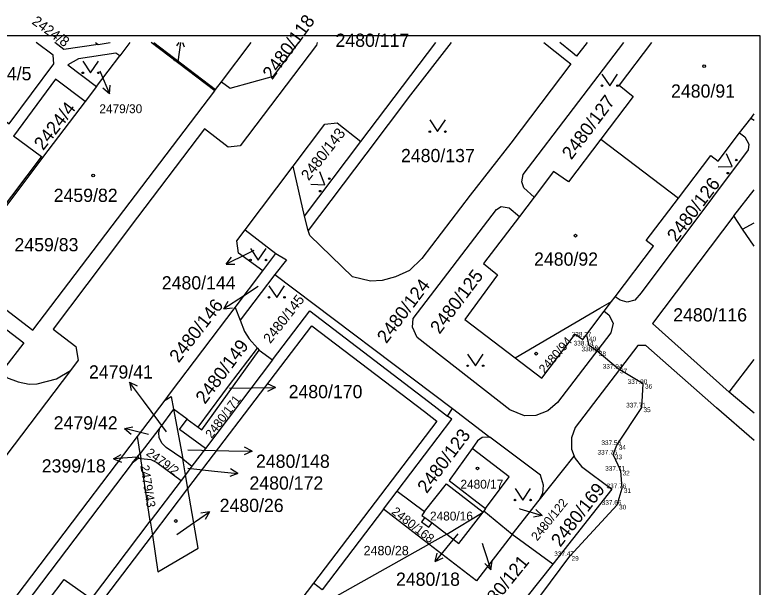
# Model space of a CAD drawing. Extents: x -606208 to -605570, y -1157873 to -1157573.
# Drawn here: x -605669 to -605573.3, y -1157647.4 to -1157573.8 of the extents above; entities that cross this region are included whole.
import ezdxf

# ---------------------------------------------------------------- set-up
doc = ezdxf.new("R2010")
doc.units = 0
for name, color, linetype in [('Vrstva 1', 7, 'Continuous'), ('Vrstva 30', 7, 'Continuous'), ('Vrstva 58', 7, 'Continuous'), ('Vrstva 59', 7, 'Continuous'), ('Vrstva 60', 7, 'Continuous'), ('Vrstva 62', 7, 'Continuous')]:
    doc.layers.add(name, color=color, linetype=linetype)

msp = doc.modelspace()

# ---------------------------------------------------------------- linework, layer by layer
at = {"layer": 'Vrstva 1'}
msp.add_lwpolyline([(-606203.28, -1157873.46), (-605573.29, -1157873.46), (-605573.29, -1157576.47), (-606203.28, -1157576.47)], close=True, dxfattribs=at)
at = {"layer": 'Vrstva 30'}
msp.add_lwpolyline([(-605601.46, -1157648.4), (-605597.74, -1157643.37), (-605591.64, -1157636.77), (-605591.02, -1157634.65), (-605591.19, -1157632.39), (-605592.18, -1157630.32), (-605591.68, -1157629.09), (-605588.5, -1157624.26), (-605588.31, -1157621.23), (-605591.51, -1157619.27), (-605594.23, -1157617.04), (-605595.25, -1157616.29), (-605595.5, -1157615.15)], dxfattribs=at)
at = {"layer": 'Vrstva 60'}
for p, q in [((-605595.5, -1157615.15), (-605595.5, -1157615.15)), ((-605595.25, -1157616.29), (-605595.25, -1157616.29)), ((-605594.23, -1157617.04), (-605594.23, -1157617.04)), ((-605591.51, -1157619.27), (-605591.51, -1157619.27)), ((-605588.31, -1157621.23), (-605588.31, -1157621.23)), ((-605588.5, -1157624.26), (-605588.5, -1157624.26)), ((-605591.68, -1157629.09), (-605591.68, -1157629.09)), ((-605592.18, -1157630.32), (-605592.18, -1157630.32)), ((-605591.19, -1157632.39), (-605591.19, -1157632.39)), ((-605591.02, -1157634.65), (-605591.02, -1157634.65)), ((-605591.64, -1157636.77), (-605591.64, -1157636.77)), ((-605597.74, -1157643.37), (-605597.74, -1157643.37))]:
    msp.add_line(p, q, dxfattribs=at)
at = {"layer": 'Vrstva 62'}
for p, q in [((-605658.68, -1157577.34), (-605658.35, -1157577.6)), ((-605658.35, -1157577.6), (-605656.81, -1157577.34)), ((-605654.27, -1157577.34), (-605655.56, -1157579.05)), ((-605643.36, -1157583.54), (-605651.52, -1157577.34)), ((-605651.18, -1157577.34), (-605643.24, -1157583.38)), ((-605647.98, -1157577.34), (-605648.28, -1157577.77)), ((-605648.06, -1157579.82), (-605647.71, -1157577.34)), ((-605647.48, -1157577.34), (-605647.29, -1157577.91)), ((-605624.6, -1157590.04), (-605614.97, -1157577.34)), ((-605658.55, -1157582.99), (-605655.56, -1157579.05)), ((-605658.13, -1157580.99), (-605658.05, -1157581.18)), ((-605658.05, -1157581.18), (-605656.877, -1157583.942)), ((-605656.877, -1157583.942), (-605656.808, -1157582.825)), ((-605643.24, -1157583.38), (-605642.49, -1157582.39)), ((-605658.55, -1157582.99), (-605660.02, -1157584.93)), ((-605656.877, -1157583.942), (-605657.73, -1157583.216)), ((-605643.36, -1157583.54), (-605643.24, -1157583.38)), ((-605660.02, -1157584.93), (-605665.48, -1157592.12)), ((-605575.92, -1157588.96), (-605574.5, -1157587.09)), ((-605665.62, -1157592.02), (-605669.22, -1157589.38)), ((-605631.83, -1157599.66), (-605624.6, -1157590.04)), ((-605593.76, -1157589.76), (-605583.79, -1157597.35)), ((-605665.48, -1157592.12), (-605676.6, -1157606.77)), ((-605665.48, -1157592.12), (-605665.62, -1157592.02)), ((-605639.44, -1157601.41), (-605633.29, -1157593.25)), ((-605631.83, -1157599.66), (-605633.29, -1157593.25)), ((-605602.33, -1157597.22), (-605604.21, -1157599.69)), ((-605631.37, -1157601.51), (-605631.83, -1157599.66)), ((-605575.53, -1157601.33), (-605576.67, -1157599.63)), ((-605575.53, -1157601.33), (-605574.07, -1157600.52)), ((-605639.44, -1157601.41), (-605635.52, -1157604.45)), ((-605639.19, -1157604.51), (-605641.887, -1157605.826)), ((-605638.32, -1157604.09), (-605639.19, -1157604.51)), ((-605637.18, -1157606.68), (-605635.52, -1157604.45)), ((-605641.887, -1157605.826), (-605641.207, -1157604.936)), ((-605641.887, -1157605.826), (-605640.768, -1157605.837)), ((-605640.74, -1157611.39), (-605637.18, -1157606.68)), ((-605635.64, -1157607.15), (-605640.08, -1157613.05)), ((-605635.64, -1157607.15), (-605612.79, -1157624.41)), ((-605637.78, -1157608.71), (-605639.67, -1157609.93)), ((-605639.67, -1157609.93), (-605642.187, -1157611.564)), ((-605642.187, -1157611.564), (-605641.62, -1157610.599)), ((-605592.38, -1157610.65), (-605591.9, -1157610.02)), ((-605642.187, -1157611.564), (-605641.074, -1157611.439)), ((-605640.74, -1157611.39), (-605640.08, -1157613.05)), ((-605593.32, -1157611.89), (-605592.38, -1157610.65)), ((-605646.81, -1157634.69), (-605630.89, -1157613.78)), ((-605630.89, -1157613.78), (-605616.42, -1157624.79)), ((-605637.86, -1157616.65), (-605637.63, -1157616.91)), ((-605637.63, -1157616.91), (-605635.93, -1157618.15)), ((-605635.93, -1157618.15), (-605644.56, -1157629.53)), ((-605577.25, -1157622.29), (-605574.07, -1157618.1)), ((-605661.91, -1157619.51), (-605672.83, -1157633.91)), ((-605652.51, -1157623.39), (-605654.316, -1157620.993)), ((-605654.316, -1157620.993), (-605653.313, -1157621.492)), ((-605654.316, -1157620.993), (-605654.113, -1157622.094)), ((-605641.46, -1157621.77), (-605638.57, -1157621.74)), ((-605638.57, -1157621.74), (-605635.569, -1157621.688)), ((-605635.569, -1157621.688), (-605636.58, -1157621.204)), ((-605635.569, -1157621.688), (-605636.562, -1157622.206)), ((-605653.28, -1157627.99), (-605649.74, -1157623.3)), ((-605649.54, -1157627.39), (-605652.51, -1157623.39)), ((-605648.64, -1157624.47), (-605650.4, -1157626.89)), ((-605646.89, -1157625.75), (-605648.64, -1157624.47)), ((-605648.64, -1157624.47), (-605647.47, -1157630.88)), ((-605616.42, -1157624.79), (-605614.81, -1157626.01)), ((-605613.46, -1157625.36), (-605612.79, -1157624.41)), ((-605612.79, -1157624.41), (-605608.01, -1157628.06)), ((-605646.89, -1157625.75), (-605645.48, -1157626.78)), ((-605654.962, -1157626.984), (-605653.869, -1157626.74)), ((-605650.4, -1157626.89), (-605652.95, -1157630.16)), ((-605614.81, -1157626.01), (-605630.66, -1157646.86)), ((-605652.05, -1157627.71), (-605654.962, -1157626.984)), ((-605654.962, -1157626.984), (-605654.111, -1157627.712)), ((-605651.89, -1157627.75), (-605652.05, -1157627.71)), ((-605652.95, -1157630.16), (-605653.28, -1157627.99)), ((-605646.81, -1157629.7), (-605641.56, -1157629.83)), ((-605644.56, -1157629.53), (-605646.3, -1157631.82)), ((-605638.559, -1157629.882), (-605639.552, -1157629.364)), ((-605610.28, -1157629.53), (-605613.26, -1157633.64)), ((-605605.51, -1157633.16), (-605610.28, -1157629.53)), ((-605656.354, -1157630.859), (-605655.39, -1157630.29)), ((-605653.36, -1157630.65), (-605656.354, -1157630.859)), ((-605653.95, -1157631.43), (-605652.95, -1157630.16)), ((-605653.12, -1157630.63), (-605653.36, -1157630.65)), ((-605652.95, -1157630.16), (-605652.85, -1157630.8)), ((-605641.56, -1157629.83), (-605638.559, -1157629.882)), ((-605638.559, -1157629.882), (-605639.57, -1157630.366)), ((-605601.66, -1157636.19), (-605597.18, -1157630.51)), ((-605653.95, -1157631.43), (-605678, -1157663.1)), ((-605656.354, -1157630.859), (-605655.32, -1157631.289)), ((-605651.64, -1157638.87), (-605652.85, -1157630.8)), ((-605647.12, -1157632.9), (-605647.47, -1157630.88)), ((-605647.47, -1157630.88), (-605646.3, -1157631.82)), ((-605646.3, -1157631.82), (-605647.12, -1157632.9)), ((-605646.81, -1157632.05), (-605643.37, -1157632.43)), ((-605643.37, -1157632.43), (-605640.385, -1157632.744)), ((-605640.385, -1157632.744), (-605641.329, -1157632.141)), ((-605647.12, -1157632.9), (-605647.67, -1157633.63)), ((-605640.385, -1157632.744), (-605641.434, -1157633.137)), ((-605608.58, -1157637.23), (-605605.51, -1157633.16)), ((-605647.67, -1157633.63), (-605651.64, -1157638.87)), ((-605613.26, -1157633.64), (-605608.58, -1157637.23)), ((-605651.37, -1157640.68), (-605646.81, -1157634.69)), ((-605621.69, -1157637.35), (-605619.9, -1157635)), ((-605619.9, -1157635), (-605616.39, -1157637.64)), ((-605605.14, -1157640.61), (-605601.66, -1157636.19)), ((-605615.84, -1157641.85), (-605621.69, -1157637.35)), ((-605608.58, -1157637.23), (-605608.77, -1157637.61)), ((-605604.18, -1157637.29), (-605604.19, -1157637.29)), ((-605604.18, -1157637.29), (-605601.31, -1157638.167)), ((-605601.31, -1157638.167), (-605602.121, -1157637.396)), ((-605646.51, -1157639.41), (-605644.052, -1157637.689)), ((-605644.052, -1157637.689), (-605645.159, -1157637.853)), ((-605644.052, -1157637.689), (-605644.585, -1157638.673)), ((-605613.53, -1157640.56), (-605608.86, -1157637.72)), ((-605608.86, -1157637.72), (-605608.77, -1157637.61)), ((-605605.14, -1157640.61), (-605608.77, -1157637.61)), ((-605601.31, -1157638.167), (-605602.414, -1157638.353)), ((-605659.2, -1157648.85), (-605651.64, -1157638.87)), ((-605651.64, -1157638.87), (-605651.37, -1157640.68)), ((-605616.35, -1157638.41), (-605615.44, -1157639.1)), ((-605648.21, -1157640.58), (-605646.51, -1157639.41)), ((-605665.1, -1157658.71), (-605651.37, -1157640.68)), ((-605613.53, -1157640.56), (-605615.84, -1157641.85)), ((-605612.13, -1157640.52), (-605613.14, -1157641.74)), ((-605599.92, -1157644.4), (-605605.14, -1157640.61)), ((-605635, -1157652.57), (-605615.84, -1157641.85)), ((-605613.14, -1157641.74), (-605615.029, -1157644.072)), ((-605609, -1157641.72), (-605608.81, -1157642.28)), ((-605615.029, -1157644.072), (-605614.787, -1157642.979)), ((-605608.81, -1157642.28), (-605607.883, -1157645.134)), ((-605615.029, -1157644.072), (-605614.009, -1157643.609)), ((-605607.883, -1157645.134), (-605607.716, -1157644.027)), ((-605607.883, -1157645.134), (-605608.668, -1157644.336))]:
    msp.add_line(p, q, dxfattribs=at)
for points in [[(-605673.74, -1157584.77), (-605669.75, -1157587.77), (-605664.04, -1157580.08), (-605664.11, -1157578.97), (-605666.29, -1157577.34)], [(-605630.18, -1157577.34), (-605630.3, -1157577.66), (-605640.08, -1157590.61), (-605641.63, -1157590.78), (-605644.67, -1157588.42), (-605654.21, -1157601.03), (-605655.48, -1157602.72), (-605664.11, -1157614.19), (-605661.21, -1157616.41), (-605660.89, -1157618.17), (-605661.91, -1157619.51)], [(-605658.35, -1157577.6), (-605662.74, -1157578.25), (-605663.92, -1157577.34)], [(-605642.49, -1157582.39), (-605641.37, -1157583.22), (-605635.79, -1157581.67), (-605632.55, -1157577.34)], [(-605642.49, -1157582.39), (-605638.66, -1157577.34)], [(-605601.08, -1157577.34), (-605598.15, -1157579.64), (-605597.61, -1157580.06), (-605605.32, -1157590.27), (-605610.52, -1157596.98), (-605616.76, -1157605.09), (-605618.34, -1157606.66), (-605620.14, -1157607.48), (-605621.84, -1157607.95), (-605623.33, -1157608.01), (-605625.65, -1157607.48), (-605631.14, -1157602.16), (-605631.37, -1157601.51)], [(-605612.99, -1157577.34), (-605618.2, -1157584.07), (-605623.94, -1157591.71), (-605631.37, -1157601.51)], [(-605602.33, -1157597.22), (-605603.63, -1157596.02), (-605603.9, -1157595.23), (-605603.75, -1157594.31), (-605590.8, -1157577.34)], [(-605595.52, -1157577.34), (-605596.86, -1157579.11), (-605597.45, -1157578.63), (-605599.02, -1157577.34)], [(-605587.25, -1157577.34), (-605591.41, -1157582.81), (-605589.6, -1157584.26), (-605593.76, -1157589.76)], [(-605655.56, -1157579.05), (-605655.7, -1157578.94), (-605656.05, -1157578.7), (-605660.88, -1157579.45), (-605662.25, -1157580.2), (-605658.55, -1157582.99)], [(-605660.31, -1157579.729), (-605659.31, -1157581.23), (-605658.31, -1157579.729)], [(-605593.61, -1157581.389), (-605592.61, -1157582.89), (-605591.61, -1157581.389)], [(-605660.02, -1157584.93), (-605663.8, -1157582.06), (-605669.22, -1157589.38)], [(-605676.6, -1157606.77), (-605666.72, -1157614.32), (-605643.36, -1157583.54)], [(-605574.5, -1157587.09), (-605574.07, -1157586.52)], [(-605615.72, -1157587.289), (-605614.72, -1157588.79), (-605613.72, -1157587.289)], [(-605574.07, -1157587.37), (-605574.5, -1157587.09)], [(-605633.29, -1157593.25), (-605629.23, -1157587.85), (-605627.63, -1157587.68), (-605624.6, -1157590.04)], [(-605575.92, -1157588.96), (-605575.25, -1157589.48), (-605574.72, -1157590.42), (-605574.83, -1157591.15), (-605588.58, -1157609.52), (-605589.39, -1157610.47), (-605590.37, -1157610.7), (-605591.27, -1157610.45), (-605591.9, -1157610.02)], [(-605583.79, -1157597.35), (-605579.63, -1157591.88), (-605578.68, -1157592.6), (-605575.92, -1157588.96)], [(-605593.76, -1157589.76), (-605597.92, -1157595.26), (-605599.83, -1157593.92), (-605602.33, -1157597.22)], [(-605676.74, -1157606.66), (-605672.06, -1157600.5), (-605671.32, -1157599.52), (-605665.62, -1157592.02)], [(-605578.694, -1157593.311), (-605576.89, -1157593.29), (-605577.604, -1157591.633)], [(-605631.032, -1157595.567), (-605629.23, -1157595.64), (-605629.857, -1157593.948)], [(-605576.67, -1157599.63), (-605574.07, -1157596.28)], [(-605591.9, -1157610.02), (-605586.98, -1157603.54), (-605587.94, -1157602.81), (-605583.79, -1157597.35)], [(-605593.32, -1157611.89), (-605592.71, -1157612.36), (-605592.17, -1157613.43), (-605592.45, -1157614.66), (-605599.33, -1157623.62), (-605600.55, -1157624.71), (-605602.09, -1157625.3), (-605603.55, -1157625.35), (-605605.43, -1157624.56), (-605617.35, -1157615.28), (-605617.94, -1157613.95), (-605617.86, -1157612.8), (-605607.16, -1157598.8), (-605606.55, -1157598.41), (-605605.53, -1157598.59), (-605604.21, -1157599.69)], [(-605604.21, -1157599.69), (-605608.81, -1157605.76), (-605607.03, -1157607.22), (-605611.22, -1157612.94), (-605604.74, -1157617.89)], [(-605576.67, -1157599.63), (-605587.11, -1157613.48), (-605577.25, -1157622.29)], [(-605637.18, -1157606.68), (-605640.31, -1157604.4), (-605640.51, -1157602.84), (-605639.44, -1157601.41)], [(-605574.07, -1157603.5), (-605575.53, -1157601.33)], [(-605638.77, -1157603.809), (-605637.77, -1157605.31), (-605636.77, -1157603.809)], [(-605635.52, -1157604.45), (-605634.14, -1157605.27), (-605635.64, -1157607.15)], [(-605682.91, -1157610.77), (-605680.85, -1157611.22), (-605678.31, -1157608.04), (-605667.9, -1157615.94), (-605670.34, -1157619.11), (-605670.1, -1157620.41)], [(-605636.39, -1157608.609), (-605635.39, -1157610.11), (-605634.39, -1157608.609)], [(-605649.74, -1157623.3), (-605649.03, -1157622.36), (-605640.74, -1157611.39)], [(-605604.74, -1157617.89), (-605593.89, -1157611.49), (-605592.38, -1157610.65)], [(-605635.93, -1157618.15), (-605631.14, -1157611.83), (-605615.17, -1157624.05), (-605613.46, -1157625.36)], [(-605604.74, -1157617.89), (-605601.32, -1157620.5), (-605597.05, -1157614.82), (-605596.08, -1157615.53), (-605593.32, -1157611.89)], [(-605640.08, -1157613.05), (-605639.52, -1157614.5), (-605638.94, -1157615.43), (-605637.86, -1157616.65)], [(-605574.07, -1157628.5), (-605578.88, -1157624.3), (-605587.98, -1157616.27), (-605589.01, -1157616.29), (-605597.05, -1157626.84), (-605597.54, -1157628.18), (-605597.52, -1157629.6), (-605597.18, -1157630.51)], [(-605645.48, -1157626.78), (-605642.31, -1157622.5), (-605641.58, -1157621.54), (-605637.86, -1157616.65)], [(-605645.48, -1157626.78), (-605645.02, -1157627.12), (-605637.63, -1157616.91)], [(-605610.87, -1157617.399), (-605609.87, -1157618.9), (-605608.87, -1157617.399)], [(-605670.1, -1157620.41), (-605668.62, -1157620.98), (-605667.18, -1157621.28), (-605666.16, -1157621.2), (-605663.7, -1157620.59), (-605661.91, -1157619.51)], [(-605649.74, -1157623.3), (-605648.94, -1157622.84), (-605648.64, -1157624.47)], [(-605574.07, -1157625), (-605577.25, -1157622.29)], [(-605644.56, -1157629.53), (-605647.87, -1157627.08), (-605646.89, -1157625.75)], [(-605619.9, -1157635), (-605612.91, -1157625.78), (-605613.46, -1157625.36)], [(-605647.47, -1157630.88), (-605649.59, -1157629.4), (-605650.16, -1157628.86), (-605650.49, -1157628.14), (-605650.54, -1157627.51), (-605650.4, -1157626.89)], [(-605714.75, -1157700.25), (-605710.96, -1157695.68), (-605710.18, -1157694.65), (-605706.94, -1157690.4), (-605702.43, -1157684.48), (-605699.9, -1157681.15), (-605696.13, -1157676.2), (-605691.65, -1157670.31), (-605690.12, -1157670.1), (-605687.04, -1157672.45), (-605682.78, -1157666.84), (-605681.4, -1157665.03), (-605679.37, -1157662.36), (-605660.55, -1157637.61), (-605653.28, -1157627.99)], [(-605608.01, -1157628.06), (-605609.01, -1157628.12), (-605609.61, -1157628.53), (-605610.28, -1157629.53)], [(-605601.66, -1157636.19), (-605601.2, -1157635.26), (-605601.1, -1157634.23), (-605601.5, -1157632.97), (-605608.01, -1157628.06)], [(-605597.18, -1157630.51), (-605597.06, -1157630.83), (-605596.22, -1157631.85), (-605592.35, -1157634.77), (-605599.92, -1157644.4)], [(-605652.85, -1157630.8), (-605653.19, -1157630.84), (-605653.95, -1157631.43)], [(-605652.85, -1157630.8), (-605651.56, -1157630.93), (-605650.78, -1157631.35), (-605647.67, -1157633.63)], [(-605645.47, -1157642.33), (-605646.81, -1157634.69), (-605647.12, -1157632.9)], [(-605616.39, -1157637.64), (-605613.6, -1157634.08), (-605608.86, -1157637.72)], [(-605604.77, -1157634.659), (-605603.77, -1157636.16), (-605602.77, -1157634.659)], [(-605621.69, -1157637.35), (-605629.56, -1157647.72), (-605630.66, -1157646.86), (-605635, -1157652.57)], [(-605616.39, -1157637.64), (-605616.77, -1157638.13), (-605616.35, -1157638.41), (-605616.78, -1157638.96), (-605615.86, -1157639.66), (-605615.44, -1157639.1), (-605613.53, -1157640.56)], [(-605613.53, -1157640.56), (-605612.01, -1157641.73), (-605608.86, -1157637.72)], [(-605651.37, -1157640.68), (-605650.66, -1157645.38), (-605645.47, -1157642.33)], [(-605605.14, -1157640.61), (-605609.72, -1157646.56), (-605615.84, -1157641.85)], [(-605599.92, -1157644.4), (-605604.92, -1157650.72), (-605630.66, -1157663.56)], [(-605661.22, -1157651.51), (-605664.71, -1157649.03), (-605662.71, -1157646.36), (-605659.2, -1157648.85)]]:
    msp.add_lwpolyline(points, dxfattribs=at)
for centre, radius in [((-605648.435, -1157579.589), 0.117), ((-605580.487, -1157580.359), 0.175), ((-605660.31, -1157581.229), 0.1), ((-605658.31, -1157581.229), 0.1), ((-605593.61, -1157582.889), 0.1), ((-605591.61, -1157582.889), 0.1), ((-605615.72, -1157588.789), 0.1), ((-605613.72, -1157588.789), 0.1), ((-605576.346, -1157592.451), 0.1), ((-605658.977, -1157594.429), 0.175), ((-605577.435, -1157594.128), 0.1), ((-605628.643, -1157594.831), 0.1), ((-605629.818, -1157596.449), 0.1), ((-605597.017, -1157602.169), 0.175), ((-605638.77, -1157605.309), 0.1), ((-605636.77, -1157605.309), 0.1), ((-605636.39, -1157610.109), 0.1), ((-605634.39, -1157610.109), 0.1), ((-605602.077, -1157617.339), 0.175), ((-605610.87, -1157618.899), 0.1), ((-605608.87, -1157618.899), 0.1), ((-605609.587, -1157632.089), 0.175), ((-605604.77, -1157636.159), 0.1), ((-605602.77, -1157636.159), 0.1), ((-605648.357, -1157638.859), 0.175)]:
    msp.add_circle(centre, radius, dxfattribs=at)

# ---------------------------------------------------------------- texts
at = {"layer": 'Vrstva 58'}
for s, p in [('338.37 ', (-605597.5, -1157615.15)), ('338.14 ', (-605597.25, -1157616.29)), ('338.11 ', (-605596.23, -1157617.04)), ('337.94 ', (-605593.51, -1157619.27)), ('337.90 ', (-605590.31, -1157621.23)), ('337.71 ', (-605590.5, -1157624.26)), ('337.56 ', (-605593.68, -1157629.09)), ('337.75 ', (-605594.18, -1157630.32)), ('337.71 ', (-605593.19, -1157632.39)), ('337.76 ', (-605593.02, -1157634.65)), ('337.66 ', (-605593.64, -1157636.77)), ('337.47 ', (-605599.74, -1157643.37))]:
    msp.add_text(s, height=0.6, dxfattribs=at).set_placement(p)
at = {"layer": 'Vrstva 59'}
for s, p in [(' 40', (-605595.5, -1157615.75)), (' 39', (-605595.25, -1157616.89)), (' 38', (-605594.23, -1157617.64)), (' 37', (-605591.51, -1157619.87)), (' 36', (-605588.31, -1157621.83)), (' 35', (-605588.5, -1157624.86)), (' 34', (-605591.68, -1157629.69)), (' 33', (-605592.18, -1157630.92)), (' 32', (-605591.19, -1157632.99)), (' 31', (-605591.02, -1157635.25)), (' 30', (-605591.64, -1157637.37)), (' 29', (-605597.74, -1157643.97))]:
    msp.add_text(s, height=0.6, dxfattribs=at).set_placement(p)
at = {"layer": 'Vrstva 62'}
for s, height, rotation, p in [('2424/8', 1.304, 324, (-605666.95, -1157574.85)), ('2480/118', 1.7, 54, (-605635.981, -1157582.216)), ('2480/127', 1.7, 53, (-605597.539, -1157592.505)), ('2424/4', 1.7, 52, (-605665.4, -1157591.3)), ('2480/143', 1.4, 52, (-605631.29, -1157595.174)), ('2480/126', 1.7, 53, (-605584.043, -1157603.087)), ('2480/125', 1.7, 53, (-605614.471, -1157614.915)), ('2480/124', 1.7, 53, (-605621.303, -1157616.127)), ('2480/146', 1.7, 52, (-605648.001, -1157618.624)), ('2480/145', 1.3, 52, (-605636.216, -1157616.12)), ('2480/94', 1.139, 49, (-605600.98, -1157619.96)), ('2480/149', 1.7, 53, (-605644.61, -1157623.92)), ('2480/171', 1.14, 53, (-605643.759, -1157628.313)), ('2480/123', 1.7, 53, (-605616.116, -1157635.407)), ('2479/2', 1.14, 324, (-605652.26, -1157630.31)), ('2479/43', 1.139, 279, (-605652.927, -1157631.746)), ('2480/169', 1.7, 52, (-605598.961, -1157642.294)), ('2480/122', 1.139, 51, (-605601.926, -1157641.494)), ('2480/168', 1.14, 322, (-605620.732, -1157637.841)), ('2480/121', 1.7, 51, (-605608.82, -1157651.515))]:
    msp.add_text(s, height=height, rotation=rotation, dxfattribs=at).set_placement(p)
for s, height, p in [('2480/117', 1.7, (-605627.84, -1157577.89)), ('2424/5', 1.7, (-605673.86, -1157582.19)), ('2480/91', 1.7, (-605584.73, -1157584.42)), ('2479/30', 1.139, (-605658.18, -1157586.419)), ('2480/137', 1.7, (-605619.427, -1157592.72)), ('2459/82', 1.7, (-605664.05, -1157597.83)), ('2459/83', 1.7, (-605669.09, -1157604.18)), ('2480/92', 1.7, (-605602.33, -1157606.03)), ('2480/144', 1.7, (-605650.16, -1157609.08)), ('2480/116', 1.7, (-605584.452, -1157613.2)), ('2479/41', 1.7, (-605659.517, -1157620.54)), ('2480/170', 1.7, (-605633.867, -1157623.07)), ('2479/42', 1.7, (-605664.049, -1157627.09)), ('2480/148', 1.7, (-605638.06, -1157632.02)), ('2399/18', 1.7, (-605665.584, -1157632.62)), ('2480/172', 1.7, (-605638.894, -1157634.82)), ('2480/17', 1.139, (-605611.79, -1157634.7)), ('2480/26', 1.7, (-605642.723, -1157637.7)), ('2480/16', 1.139, (-605615.7, -1157638.79)), ('2480/28', 1.2, (-605624.23, -1157643.26)), ('2480/18', 1.7, (-605620.071, -1157647.19))]:
    msp.add_text(s, height=height, dxfattribs=at).set_placement(p)

doc.saveas('drawing.dxf')
